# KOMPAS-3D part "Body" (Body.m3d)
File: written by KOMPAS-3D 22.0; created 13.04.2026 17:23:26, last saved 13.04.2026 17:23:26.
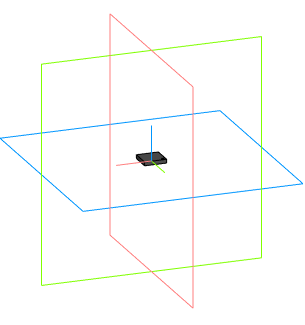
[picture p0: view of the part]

Document properties: Автор: Andrey; Полное имя файла: C:\Users\User1\Documents\Body.m3d

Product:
- Part/product: Body

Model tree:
1. Операция без истории:1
